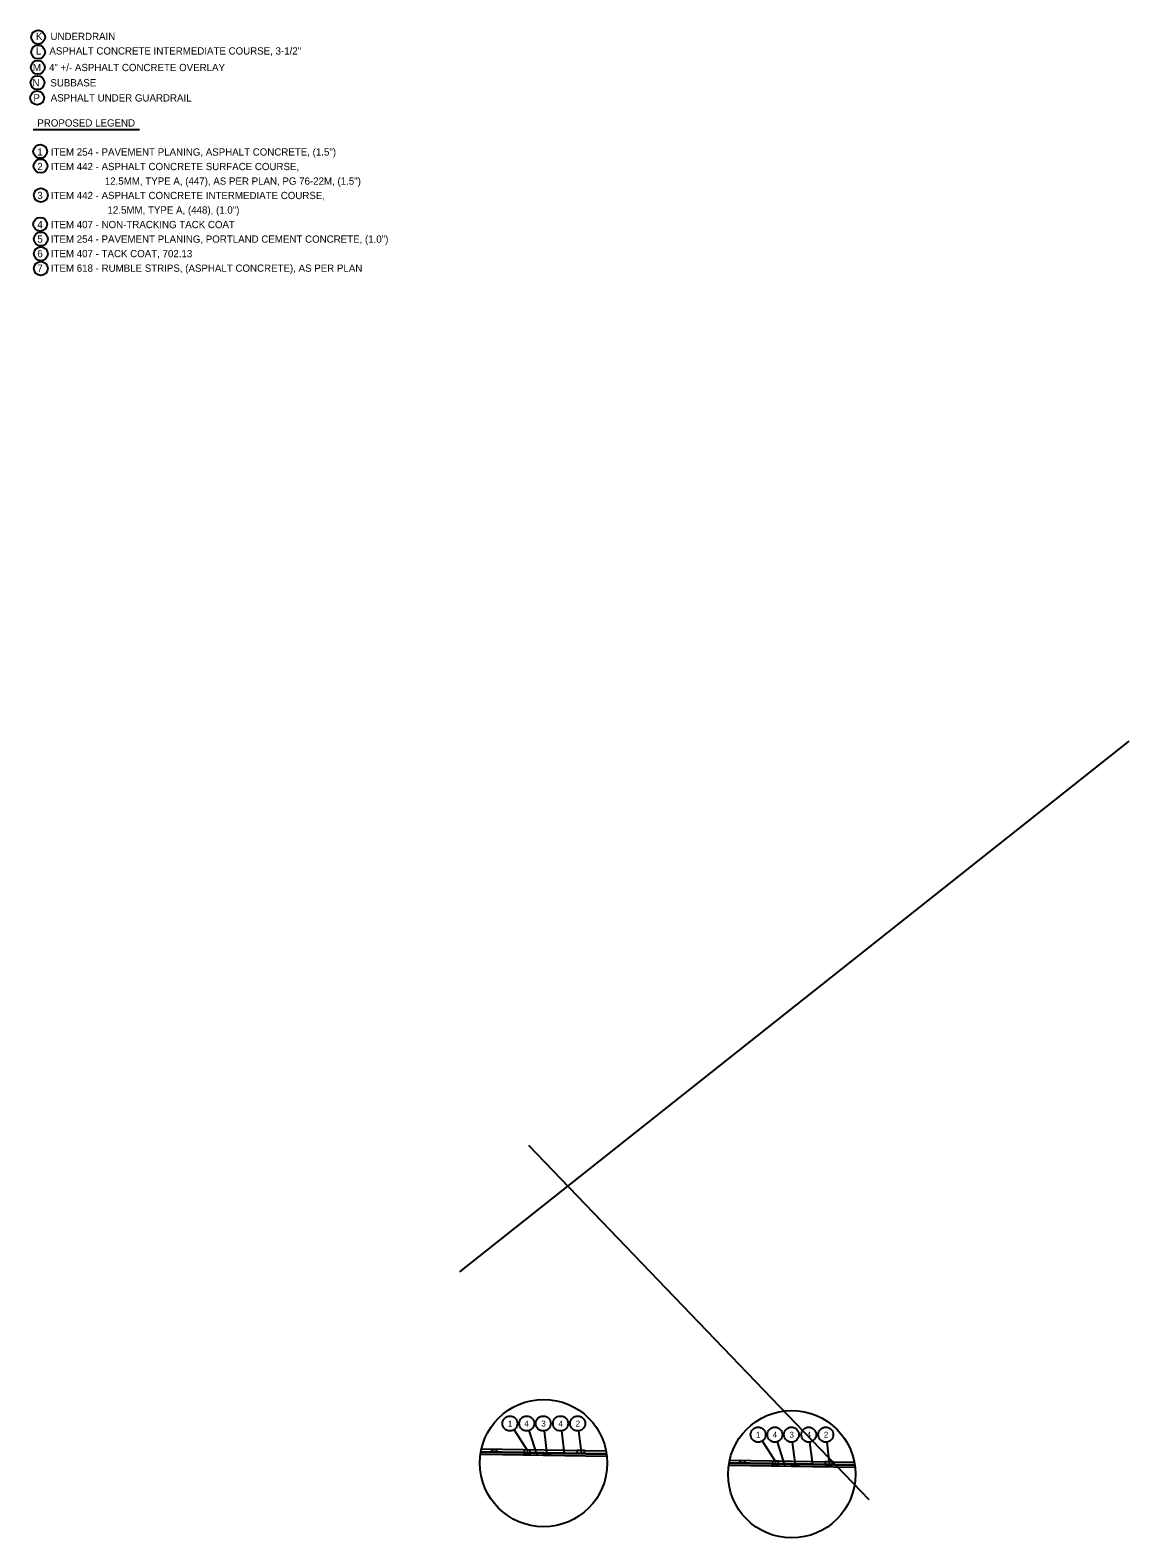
# Model space of a CAD drawing. Extents: x -210 to 558, y -150 to 205.
# Drawn here: x -101.3 to 0, y -73.5 to 65.6 of the extents above; entities that cross this region are included whole.
import ezdxf

# ---------------------------------------------------------------- set-up
doc = ezdxf.new("R2010")
doc.units = 0
for name, color, linetype in [('Level 1', 7, 'Continuous'), ('Level 59', 7, 'Continuous'), ('SC_Scratch1', 7, 'Continuous')]:
    doc.layers.add(name, color=color, linetype=linetype)

msp = doc.modelspace()

# ---------------------------------------------------------------- linework, layer by layer
at = {"layer": 'Level 1'}
for p, q in [((-55.32, -37.28), (-55.32, -37.28)), ((-56.69, -63.5), (-55.42, -65.46)), ((-55.31, -63.57), (-54.6, -65.81)), ((-53.91, -63.6), (-53.65, -65.73)), ((-52.31, -63.6), (-52.06, -65.67)), ((-50.74, -63.6), (-50.5, -65.55)), ((-59.68, -65.26), (-48.15, -65.44)), ((-33.81, -64.52), (-32.54, -66.49)), ((-32.43, -64.6), (-31.72, -66.84)), ((-31.03, -64.62), (-30.77, -66.75)), ((-29.43, -64.62), (-29.18, -66.69)), ((-27.86, -64.62), (-27.62, -66.57)), ((-59.73, -65.5), (-48.16, -65.68)), ((-59.69, -65.54), (-48.16, -65.73)), ((-59.69, -65.73), (-48.16, -65.92)), ((-36.85, -66.52), (-25.28, -66.7)), ((-36.8, -66.29), (-25.27, -66.47)), ((-36.8, -66.57), (-25.28, -66.75)), ((-36.81, -66.76), (-25.28, -66.94))]:
    msp.add_line(p, q, dxfattribs=at)
for points in [[(-58.72, -65.28), (-58.3, -65.28), (-58.3, -65.52), (-58.72, -65.51)], [(-55.71, -65.32), (-55.22, -65.33), (-55.23, -65.8), (-55.72, -65.8)], [(-53.97, -65.82), (-53.34, -65.83), (-53.33, -65.64), (-53.97, -65.63)], [(-50.89, -65.68), (-50.19, -65.69), (-50.19, -65.41), (-50.88, -65.4)], [(-35.84, -66.3), (-35.42, -66.31), (-35.42, -66.54), (-35.84, -66.54)], [(-32.83, -66.35), (-32.34, -66.36), (-32.35, -66.83), (-32.84, -66.82)], [(-31.09, -66.85), (-30.46, -66.86), (-30.45, -66.67), (-31.09, -66.66)], [(-28.01, -66.71), (-27.31, -66.72), (-27.31, -66.44), (-28, -66.43)]]:
    msp.add_lwpolyline(points, close=True, dxfattribs=at)
for centre, radius in [((-53.96, -66.56), 5.87), ((-57.06, -62.91), 0.691), ((-55.52, -62.91), 0.691), ((-53.99, -62.91), 0.691), ((-52.4, -62.91), 0.691), ((-50.82, -62.91), 0.691), ((-31.08, -67.59), 5.87), ((-34.18, -63.94), 0.691), ((-32.64, -63.94), 0.691), ((-31.11, -63.94), 0.691), ((-29.52, -63.94), 0.691), ((-27.94, -63.94), 0.691)]:
    msp.add_circle(centre, radius, dxfattribs=at)
at = {"layer": 'Level 59'}
msp.add_line((-101.01, 56.42), (-91.21, 56.42), dxfattribs=at)
for centre in [(-100.57, 64.93), (-100.57, 63.55), (-100.6, 62.14), (-100.63, 60.73), (-100.66, 59.32), (-100.37, 54.39), (-100.34, 53.04), (-100.32, 50.35), (-100.37, 47.67), (-100.32, 46.31), (-100.32, 44.95), (-100.32, 43.59)]:
    msp.add_circle(centre, 0.639, dxfattribs=at)
at = {"layer": 'SC_Scratch1'}
for p, q in [((0, 0), (-61.73, -48.93)), ((-23.94, -69.96), (-55.32, -37.28))]:
    msp.add_line(p, q, dxfattribs=at)

# ---------------------------------------------------------------- texts
at = {"layer": 'Level 1'}
for s, p in [('1', (-57.26, -63.19)), ('4', (-55.73, -63.19)), ('3', (-54.17, -63.19)), ('4', (-52.58, -63.19)), ('2', (-51, -63.19)), ('1', (-34.38, -64.22)), ('4', (-32.84, -64.22)), ('3', (-31.29, -64.22)), ('4', (-29.7, -64.22)), ('2', (-28.12, -64.22))]:
    msp.add_text(s, height=0.547, dxfattribs=at).set_placement(p)
at = {"layer": 'Level 59'}
for s, p in [('K   UNDERDRAIN ', (-100.77, 64.66)), ('L   ASPHALT CONCRETE INTERMEDIATE COURSE, 3-1/2"          ', (-100.77, 63.32)), ('M   4" +/- ASPHALT CONCRETE OVERLAY   ', (-101.05, 61.79)), ('N    SUBBASE', (-101.08, 60.38)), ('P    ASPHALT UNDER GUARDRAIL', (-101, 58.99)), ('PROPOSED LEGEND', (-100.64, 56.68)), ('1   ITEM 254 - PAVEMENT PLANING, ASPHALT CONCRETE, (1.5")', (-100.64, 54)), ('2   ITEM 442 - ASPHALT CONCRETE SURFACE COURSE,', (-100.64, 52.66)), ('                         12.5MM, TYPE A, (447), AS PER PLAN, PG 76-22M, (1.5")', (-100.64, 51.32)), ('3   ITEM 442 - ASPHALT CONCRETE INTERMEDIATE COURSE,', (-100.64, 49.99)), ('                          12.5MM, TYPE A, (448), (1.0")', (-100.64, 48.65)), ('4   ITEM 407 - NON-TRACKING TACK COAT', (-100.64, 47.31)), ('5   ITEM 254 - PAVEMENT PLANING, PORTLAND CEMENT CONCRETE, (1.0")', (-100.64, 45.97)), ('6   ITEM 407 - TACK COAT, 702.13', (-100.64, 44.63)), ('7   ITEM 618 - RUMBLE STRIPS, (ASPHALT CONCRETE), AS PER PLAN', (-100.64, 43.29))]:
    msp.add_text(s, height=0.6698, dxfattribs=at).set_placement(p)

doc.saveas('drawing.dxf')
